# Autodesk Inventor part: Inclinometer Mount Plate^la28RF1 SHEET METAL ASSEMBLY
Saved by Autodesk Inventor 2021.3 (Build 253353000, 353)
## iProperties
Created: 2023-01
Part Number: Inclinometer Mount Plate^la28RF1 SHEET METAL ASSEMBLY
Material: Generic
Document SubType Name: Modeling
Designer: AdminForWorker
Density: 1 g/cm^3
Appearance: Default
Title: Inclinometer Mount Plate^la28RF1 SHEET METAL ASSEMBLY
Author: AdminForWorker
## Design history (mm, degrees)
feature "Cut-Extrude2"
body "Solid1"
